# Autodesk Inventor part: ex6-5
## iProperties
Shininess: 64.0
Length Units: 11272
Angle Units: 11279
Time Units: 11290
Mass Units: 11286
Length Display Precision: 3
Angle Display Precision: 2
Compacted: True
Part Number: ex6-5
Document SubType Name: Modeling
Created: 2002-11
Designer: Elise Moss
Density: 0.0
Volumn: 0.0
Area: 0.0
PropertySet Name: Model Information
Control State: 0
Master: False
Checked Out: False
Author: Elise Moss
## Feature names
1. Extrusion1
2. Extrusion2
